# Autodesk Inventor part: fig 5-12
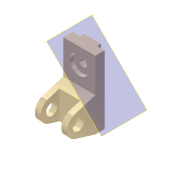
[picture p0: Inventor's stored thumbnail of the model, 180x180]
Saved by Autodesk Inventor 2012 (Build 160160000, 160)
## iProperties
Shininess: 65.0
Angle Display Precision: 2
Document Length Units: 11269
Document Angle Units: 11279
Document Time Units: 11290
Document Mass Units: 11283
Document Length Units Precision: 3
Document Angle Units Precision: 2
Compacted: False
Created: 2001-11
Part Number: fig 5-12
Document SubType Name: Modeling
Designer: Renu Muthoo
Density: 1 g/cm^3
Material: Default
Density: 0.0
Volumn: 0.0
Area: 0.0
PropertySet Name: Model Information
Control State: 0
Master: False
Checked Out: False
Author: Renu Muthoo
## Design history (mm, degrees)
node "Sketch1"
sketch "Sketch2"
  geometry: L1 (33.257, 104.664)-(33.257, -75.336); L2 (33.257, -75.336)-(8.257, -75.336); L3 (8.257, -75.336)-(-45.451, -59.045); L4 (-45.451, -1.628)-(8.257, 14.664); L5 (8.257, 14.664)-(8.257, 104.664); L6 (8.257, 104.664)-(33.257, 104.664); C1 r 15 at (-36.743, -30.336); A1 r 30 centre (-36.743, -30.336) between (-45.451, -1.628) and (-45.451, -59.045)
  constraints: 12 end point, 2 centre point, 2 equal length, 2 parallel, 2 point on circle, 2 tangent, 1 coincident, 1 perpendicular, 1 vertical
  dimensions: "d0" = 180 distance of L1.start L1.end; "d1" = 30 radius of A1; "d2" = 25 distance of L5.end L1.start; "d3" = 45 distance from line of L2 A1.centre; "d4" = 70 distance from line of L1 A1.centre; "d5" = 30 diameter of C1
extrude "Extrusion1" new body sketch "Sketch2" distance "d6" = 85; taper "d7" = 0 deg
workplane "Work Plane1"
sketch "Sketch3"
  geometry: L1 (15, 62.364)-(70, 62.364); L2 (70, 62.364)-(70, -52.386); L3 (70, -52.386)-(15, -52.386); L4 (15, -52.386)-(15, 62.364); L5 (0, -45)-(0, -28.708) reference
  constraints: 8 end point, 2 parallel, 1 horizontal, 1 perpendicular
  dimensions: "d8" = 55 distance of L1.start L1.end; "d9" = 15 distance between parallel lines of L5 L4
extrude "Extrusion2" cut sketch "Sketch3" distance "d10" = 50; taper "d11" = 0 deg
sketch "Sketch4"
  geometry: L1 (0, 25)-(85, 25) reference; L2 (0, 0)-(0, 25) reference; L3 (20, 25)-(65, 25); L4 (65, 25)-(65, 35); L5 (65, 35)-(20, 35); L6 (20, 35)-(20, 25)
  constraints: 8 end point, 2 parallel, 1 horizontal, 1 perpendicular, 1 point on line
  dimensions: "d12" = 45 distance of L4.end L5.end; "d13" = 10 distance of L3.end L4.end; "d14" = 20 distance between parallel lines of L2 L6
extrude "Extrusion3" join sketch "Sketch4" stored distance "d15" = 50; taper "d16" = 0 deg
sketch "Sketch5"
  geometry: L1 (85, 0)-(85, 90) reference; L2 (0, 90)-(85, 90) reference; 1 further point
  dimensions: "d17" = 42 distance from line of L2 point (42.5, 48); "d18" = 42.5 distance from line of L1 point (42.5, 48)
hole "Hole1" sketch "Sketch5" at (42.5, 48) diameter "d19" = 20; stored, may be unused: countersink angle "d23" = 82 deg, drill point angle "d25" = 118 deg; dims "d20" = 6, "d21" = 50, "d22" = 10, "d24" = 8
workplane "Work Plane8"
body "Solid1"
other parameters: "d28" = 135 deg
